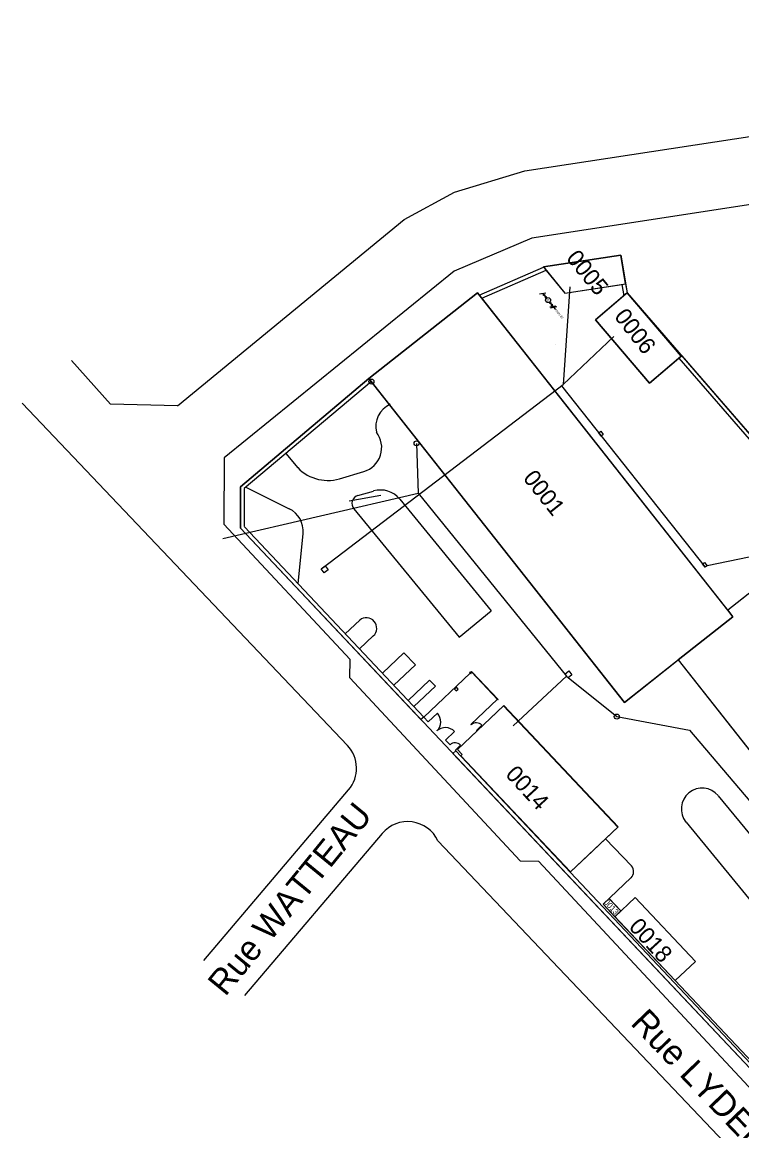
# Model space of a CAD drawing. Extents: x 703432 to 707394, y 7057985 to 7059523.
# Drawn here: x 704420.6 to 704507, y 7058975.3 to 7059108.3 of the extents above; entities that cross this region are included whole.
import ezdxf

# ---------------------------------------------------------------- set-up
doc = ezdxf.new("R2010")
doc.units = 0
for name, color, linetype in [('DH_HACHURE-MOTIF', 7, 'Continuous'), ('DH_TEXTE', 7, 'Continuous'), ('GO_MUR_EXTERIEUR', 7, 'Continuous'), ('IMM_LIMITE PHYSIQUE', 7, 'Continuous'), ('R_PLU_CANALISATION_CL_A', 7, 'Continuous'), ('RES_INCENDIE - EQUIP - TEXTE', 7, 'Continuous'), ('SID_NUMERO_BATI', 7, 'Continuous'), ('SID_POLYLIGNES_BATI', 7, 'Continuous'), ('SID_POLYLIGNES_IMMEUBLE', 7, 'Continuous'), ('VOIRIE_BORDURE', 7, 'Continuous'), ('VOIRIE_ROUTE', 7, 'Continuous')]:
    doc.layers.add(name, color=color, linetype=linetype)

msp = doc.modelspace()

# ---------------------------------------------------------------- linework, layer by layer
at = {"layer": 'DH_HACHURE-MOTIF'}
for p, q in [((704489.38, 7059072.6), (704492.8, 7059075.53)), ((704492.8, 7059075.53), (704493.18, 7059075.86)), ((704493.18, 7059075.86), (704499.68, 7059068.26)), ((704495.88, 7059065.01), (704489.38, 7059072.6))]:
    msp.add_line(p, q, dxfattribs=at)
for points in [[(704492.56, 7059076.86), (704493, 7059076.93), (704492.42, 7059080.39), (704483.15, 7059078.96), (704483.48, 7059078.55), (704485.7, 7059075.83), (704492.56, 7059076.86)], [(704462.47, 7059065.21), (704464.67, 7059062.42), (704492.86, 7059026.7), (704499.33, 7059031.81), (704505.89, 7059036.98), (704505.27, 7059037.77), (704475.53, 7059075.46), (704475.23, 7059075.84), (704462.2, 7059065.56), (704462.47, 7059065.21)], [(704499.68, 7059068.26), (704499.34, 7059067.97), (704495.88, 7059065.01)], [(704551.65, 7058991.33), (704511.27, 7059042.51), (704505.27, 7059037.77), (704505.89, 7059036.98), (704499.33, 7059031.81), (704539.09, 7058981.42), (704551.65, 7058991.33)], [(704491.09, 7059003.13), (704491.03, 7059003.2), (704490.3, 7059002.52), (704491.72, 7059001.01), (704492.45, 7059001.7), (704491.09, 7059003.13)]]:
    msp.add_lwpolyline(points, dxfattribs=at)
for points in [[(704488.34, 7059008.23), (704492.06, 7059011.74), (704478.34, 7059026.29), (704472.82, 7059021.09), (704473.4, 7059020.47), (704473.24, 7059020.31), (704486.38, 7059006.38)], [(704494.17, 7059003.32), (704491.72, 7059001.01), (704498.96, 7058993.34), (704501.41, 7058995.65)]]:
    msp.add_lwpolyline(points, close=True, dxfattribs=at)
at = {"layer": 'GO_MUR_EXTERIEUR'}
for p, q in [((704492.42, 7059080.39), (704483.15, 7059078.96)), ((704493, 7059076.93), (704492.42, 7059080.39)), ((704483.15, 7059078.96), (704485.7, 7059075.83)), ((704485.7, 7059075.83), (704493, 7059076.93)), ((704462.2, 7059065.56), (704475.23, 7059075.84)), ((704475.23, 7059075.84), (704505.89, 7059036.98)), ((704493.18, 7059075.86), (704489.38, 7059072.6)), ((704499.68, 7059068.26), (704493.18, 7059075.86)), ((704489.38, 7059072.6), (704495.88, 7059065.01)), ((704489.38, 7059072.6), (704489.38, 7059072.6)), ((704495.88, 7059065.01), (704499.68, 7059068.26)), ((704492.86, 7059026.7), (704462.2, 7059065.56)), ((704511.27, 7059042.51), (704505.27, 7059037.77)), ((704505.89, 7059036.98), (704492.86, 7059026.7)), ((704505.89, 7059036.98), (704499.33, 7059031.81)), ((704505.27, 7059037.77), (704505.89, 7059036.98)), ((704499.33, 7059031.81), (704539.09, 7058981.42)), ((704478.38, 7059026.33), (704472.82, 7059021.09)), ((704492.1, 7059011.78), (704478.38, 7059026.33)), ((704486.38, 7059006.38), (704492.1, 7059011.78)), ((704490.3, 7059002.52), (704491.03, 7059003.2)), ((704491.72, 7059001.01), (704490.3, 7059002.52)), ((704491.03, 7059003.2), (704492.45, 7059001.7)), ((704492.45, 7059001.7), (704491.72, 7059001.01))]:
    msp.add_line(p, q, dxfattribs=at)
msp.add_lwpolyline([(704472.82, 7059021.09), (704473.4, 7059020.47), (704473.24, 7059020.31), (704486.38, 7059006.38)], dxfattribs=at)
msp.add_lwpolyline([(704494.17, 7059003.32), (704501.41, 7058995.65), (704498.96, 7058993.34), (704491.72, 7059001.01)], close=True, dxfattribs=at)
at = {"layer": 'IMM_LIMITE PHYSIQUE'}
for p, q in [((704475.44, 7059075.59), (704483.17, 7059078.92)), ((704475.74, 7059075.23), (704483.48, 7059078.56)), ((704492.56, 7059076.86), (704492.78, 7059075.51)), ((704493, 7059076.93), (704493.18, 7059075.86)), ((704499.39, 7059068.01), (704511.13, 7059054.48)), ((704499.74, 7059068.3), (704511.28, 7059054.99)), ((704462.2, 7059065.56), (704446.77, 7059052.59)), ((704462.49, 7059065.21), (704447.22, 7059052.38)), ((704446.77, 7059052.59), (704446.77, 7059047.64)), ((704447.22, 7059052.38), (704447.22, 7059047.84)), ((704446.77, 7059047.64), (704468.44, 7059024.66)), ((704447.24, 7059047.8), (704468.77, 7059024.97)), ((704468.77, 7059024.97), (704474.33, 7059030.22)), ((704474.42, 7059024.09), (704477.63, 7059027.12)), ((704468.77, 7059024.97), (704468.44, 7059024.66)), ((704468.77, 7059024.97), (704469.32, 7059024.39)), ((704469.32, 7059024.39), (704470.41, 7059025.42)), ((704474.42, 7059024.09), (704474.48, 7059024.02)), ((704475.75, 7059023.99), (704475.1, 7059023.37)), ((704475.1, 7059023.37), (704475.15, 7059023.31)), ((704471.38, 7059022.2), (704472.47, 7059023.23)), ((704471.38, 7059022.2), (704471.93, 7059021.62)), ((704472.61, 7059020.9), (704472.28, 7059020.59)), ((704473.2, 7059021.58), (704472.55, 7059020.97)), ((704472.55, 7059020.97), (704472.61, 7059020.9)), ((704472.61, 7059020.9), (704536.21, 7058953.48)), ((704472.28, 7059020.59), (704535.98, 7058953.07))]:
    msp.add_line(p, q, dxfattribs=at)
for points in [[(704474.49, 7059030.37), (704474.25, 7059030.31), (704474.42, 7059030.13)], [(704474.49, 7059030.37), (704477.65, 7059027.02), (704477.69, 7059027.05), (704474.53, 7059030.4)], [(704472.46, 7059028.31), (704472.66, 7059028.09), (704472.9, 7059028.32), (704472.7, 7059028.53)]]:
    msp.add_lwpolyline(points, close=True, dxfattribs=at)
for centre, radius, start, end in [((704469.32, 7059024.39), 1.5, 313.3307, 43.3307), ((704471.38, 7059022.2), 1.5, 43.3307, 133.3307), ((704475.1, 7059023.37), 0.9, 43.3307, 133.3307), ((704472.55, 7059020.97), 0.9, 43.3307, 133.3307)]:
    msp.add_arc(centre, radius, start, end, dxfattribs=at)
at = {"layer": 'R_PLU_CANALISATION_CL_A'}
for p, q in [((704486.32, 7059076.59), (704485.51, 7059064.84)), ((704491.6, 7059070.62), (704485.51, 7059064.84)), ((704456.7, 7059042.92), (704485.51, 7059064.84)), ((704485.33, 7059064.69), (704502.56, 7059042.93)), ((704444.66, 7059046.4), (704468.09, 7059051.81)), ((704485.92, 7059029.88), (704479.51, 7059023.9)), ((704500.69, 7059023.41), (704541.03, 7058975.68))]:
    msp.add_line(p, q, dxfattribs=at)
for points in [[(704489.78, 7059059.07), (704490.02, 7059059.25), (704490.33, 7059058.86), (704490.09, 7059058.68), (704489.78, 7059059.07)], [(704572.09, 7059059.65), (704517.73, 7059046.17), (704502.8, 7059043.12)], [(704467.91, 7059057.8), (704468.09, 7059051.81), (704485.92, 7059029.88)], [(704502.25, 7059043.33), (704502.49, 7059043.51), (704502.8, 7059043.12), (704502.56, 7059042.93), (704502.25, 7059043.33)], [(704457.31, 7059042.63), (704456.84, 7059042.26), (704456.47, 7059042.73), (704456.94, 7059043.1), (704457.31, 7059042.63)], [(704486.57, 7059030.02), (704486.1, 7059029.65), (704485.73, 7059030.12), (704486.2, 7059030.49), (704486.57, 7059030.02)], [(704485.92, 7059029.88), (704491.95, 7059025.02), (704500.69, 7059023.41)]]:
    msp.add_lwpolyline(points, dxfattribs=at)
for centre in [(704483.7, 7059074.98), (704462.49, 7059065.21), (704467.91, 7059057.8), (704491.95, 7059025.02)]:
    msp.add_circle(centre, 0.3, dxfattribs=at)
at = {"layer": 'RES_INCENDIE - EQUIP - TEXTE'}
for p, q in [((704482.69, 7059075.73), (704483.43, 7059075.86)), ((704483.2, 7059075.62), (704483.06, 7059075.79)), ((704483.27, 7059075.67), (704483.13, 7059075.56)), ((704483.54, 7059075.33), (704483.13, 7059075.56)), ((704483.27, 7059075.67), (704483.4, 7059075.22)), ((704483.54, 7059075.33), (704483.4, 7059075.22)), ((704483.47, 7059075.27), (704483.51, 7059075.22)), ((704484, 7059074.74), (704483.86, 7059074.63)), ((704484.27, 7059074.4), (704483.86, 7059074.63)), ((704483.93, 7059074.69), (704483.89, 7059074.75)), ((704483.91, 7059074.18), (704484.65, 7059074.31)), ((704484, 7059074.74), (704484.13, 7059074.29)), ((704484, 7059074.07), (704484.74, 7059074.2)), ((704484.27, 7059074.4), (704484.13, 7059074.29)), ((704484.2, 7059074.35), (704484.28, 7059074.25)), ((704484.37, 7059074.13), (704484.59, 7059073.85)), ((704484.57, 7059069.64), (704484.57, 7059069.64)), ((704459.81, 7059050.9), (704463.63, 7059051.57))]:
    msp.add_line(p, q, dxfattribs=at)
msp.add_circle((704483.7, 7059074.98), 0.301, dxfattribs=at)
at = {"layer": 'SID_POLYLIGNES_BATI'}
for p, q in [((704492.42, 7059080.39), (704483.15, 7059078.96)), ((704493, 7059076.93), (704492.42, 7059080.39)), ((704483.15, 7059078.96), (704485.7, 7059075.83)), ((704485.7, 7059075.83), (704493, 7059076.93)), ((704462.2, 7059065.56), (704475.23, 7059075.84)), ((704475.23, 7059075.84), (704505.89, 7059036.98)), ((704493.18, 7059075.86), (704489.38, 7059072.6)), ((704499.68, 7059068.26), (704493.18, 7059075.86)), ((704489.38, 7059072.6), (704495.88, 7059065.01)), ((704489.38, 7059072.6), (704489.38, 7059072.6)), ((704495.88, 7059065.01), (704499.68, 7059068.26)), ((704492.86, 7059026.7), (704462.2, 7059065.56)), ((704511.27, 7059042.51), (704505.27, 7059037.77)), ((704505.89, 7059036.98), (704492.86, 7059026.7)), ((704505.89, 7059036.98), (704499.33, 7059031.81)), ((704505.27, 7059037.77), (704505.89, 7059036.98)), ((704499.33, 7059031.81), (704539.09, 7058981.42)), ((704478.34, 7059026.29), (704472.82, 7059021.09)), ((704492.06, 7059011.74), (704478.34, 7059026.29)), ((704486.38, 7059006.38), (704492.06, 7059011.74)), ((704490.3, 7059002.52), (704491.03, 7059003.2)), ((704491.72, 7059001.01), (704490.3, 7059002.52)), ((704491.03, 7059003.2), (704492.45, 7059001.7)), ((704492.45, 7059001.7), (704491.72, 7059001.01))]:
    msp.add_line(p, q, dxfattribs=at)
msp.add_lwpolyline([(704472.82, 7059021.09), (704473.4, 7059020.47), (704473.24, 7059020.31), (704486.38, 7059006.38)], dxfattribs=at)
msp.add_lwpolyline([(704494.17, 7059003.32), (704501.41, 7058995.65), (704498.96, 7058993.34), (704491.72, 7059001.01)], close=True, dxfattribs=at)
at = {"layer": 'SID_POLYLIGNES_IMMEUBLE'}
for p, q in [((704446.77, 7059047.64), (704446.77, 7059052.59)), ((704535.98, 7058953.07), (704446.77, 7059047.64))]:
    msp.add_line(p, q, dxfattribs=at)
for points in [[(704475.23, 7059075.84), (704475.44, 7059075.59), (704483.17, 7059078.92), (704483.15, 7059078.96), (704492.42, 7059080.39)], [(704492.42, 7059080.39), (704493.18, 7059075.86), (704511.28, 7059054.99)], [(704446.77, 7059052.59), (704462.2, 7059065.56), (704475.23, 7059075.84)]]:
    msp.add_lwpolyline(points, dxfattribs=at)
at = {"layer": 'VOIRIE_BORDURE'}
for p, q in [((704452.23, 7059056.59), (704453.65, 7059054.86)), ((704458.66, 7059053.56), (704461.57, 7059054.41)), ((704457.91, 7059053.34), (704457.91, 7059053.34)), ((704447.41, 7059052.54), (704452.63, 7059049.96)), ((704460.88, 7059051.54), (704462.75, 7059052.08)), ((704460.39, 7059049.95), (704473.01, 7059034.55)), ((704465.91, 7059051.11), (704476.88, 7059037.72)), ((704453.69, 7059040.96), (704454.29, 7059046.98)), ((704473.01, 7059034.55), (704476.88, 7059037.72)), ((704459.35, 7059034.95), (704461.09, 7059036.59)), ((704461.07, 7059033.14), (704462.72, 7059034.7)), ((704463.81, 7059030.23), (704466.4, 7059032.66)), ((704467.77, 7059031.21), (704466.4, 7059032.66)), ((704465.19, 7059028.77), (704467.77, 7059031.21)), ((704466.9, 7059026.95), (704469.48, 7059029.39)), ((704470.17, 7059028.66), (704469.48, 7059029.39)), ((704467.59, 7059026.22), (704470.17, 7059028.66)), ((704504.13, 7059015.53), (704523.58, 7058991.8)), ((704500.26, 7059012.37), (704519.71, 7058988.63)), ((704490.61, 7059010.37), (704493.7, 7059007.1)), ((704493.65, 7059005.68), (704490.3, 7059002.52)), ((704490.3, 7059002.52), (704508.23, 7058983.51))]:
    msp.add_line(p, q, dxfattribs=at)
for centre, radius, start, end in [((704466.02, 7059059.78), 3, 115.4761, 192.4737), ((704460.73, 7059057.29), 3, 286.3025, 37.942), ((704457.25, 7059058.35), 5, 219.5679, 286.3025), ((704461.15, 7059050.58), 1, 106.0656, 219.3307), ((704463.58, 7059049.2), 3, 39.3307, 106.0656), ((704451.3, 7059047.27), 3, 354.3306, 63.7442), ((704461.88, 7059035.63), 1.25, 312.1096, 129.3307), ((704502.19, 7059013.95), 2.5, 39.3307, 219.3307), ((704492.97, 7059006.41), 1, 313.3306, 43.3306)]:
    msp.add_arc(centre, radius, start, end, dxfattribs=at)
at = {"layer": 'VOIRIE_ROUTE'}
for p, q in [((704459.61, 7059021.56), (704420.57, 7059062.63)), ((704439.21, 7059062.29), (704431.18, 7059062.49)), ((704444.83, 7059056.07), (704444.78, 7059048.12)), ((704444.78, 7059048.12), (704459.96, 7059031.86)), ((704459.89, 7059029.65), (704459.96, 7059031.86)), ((704459.89, 7059029.65), (704480.35, 7059007.72)), ((704442.38, 7058995.75), (704459.76, 7059016.22)), ((704447.3, 7058991.57), (704463.81, 7059011.01)), ((704527.18, 7058950.47), (704470.47, 7059010.13)), ((704480.35, 7059007.72), (704482.59, 7059007.66)), ((704482.54, 7059007.66), (704534.87, 7058951.59))]:
    msp.add_line(p, q, dxfattribs=at)
for points in [[(704439.21, 7059062.29), (704466.43, 7059084.66), (704472.47, 7059087.95), (704480.92, 7059090.49), (704597.81, 7059108.33)], [(704599.06, 7059100.45), (704481.77, 7059082.41), (704472.42, 7059078.45), (704444.83, 7059056.07)], [(704431.18, 7059062.49), (704426.51, 7059067.73)]]:
    msp.add_lwpolyline(points, dxfattribs=at)
for centre, start, end in [((704456.71, 7059018.81), 319.6675, 43.547), ((704466.85, 7059008.42), 25.2763, 139.6675)]:
    msp.add_arc(centre, 4, start, end, dxfattribs=at)

# ---------------------------------------------------------------- texts
at = {"layer": 'DH_TEXTE'}
for s, rotation, p in [('Rue WATTEAU', 50.7423, (704444.95, 7058991.35)), ('Rue LYDERIC', 313.8024, (704493.48, 7058988.15))]:
    msp.add_text(s, height=3, rotation=rotation, dxfattribs=at).set_placement(p)
at = {"layer": 'RES_INCENDIE - EQUIP - TEXTE'}
for s, p in [('E', (704483.51, 7059074.99)), ('Vers BI', (704484.53, 7059073.74))]:
    msp.add_text(s, height=0.29, rotation=308.2727, dxfattribs=at).set_placement(p)
at = {"layer": 'SID_NUMERO_BATI'}
for s, height, rotation, p in [('0005', 2, 309.3307, (704485.78, 7059079.97)), ('0006', 2, 307.9879, (704491.55, 7059073)), ('0001', 2, 308.2727, (704480.61, 7059053.6)), ('0014', 2, 312.5129, (704478.48, 7059018.01)), ('0013', 0.698, 312.5129, (704490.34, 7059002.7)), ('0018', 2, 312.5129, (704493.29, 7058999.72))]:
    msp.add_text(s, height=height, rotation=rotation, dxfattribs=at).set_placement(p)

doc.saveas('drawing.dxf')
